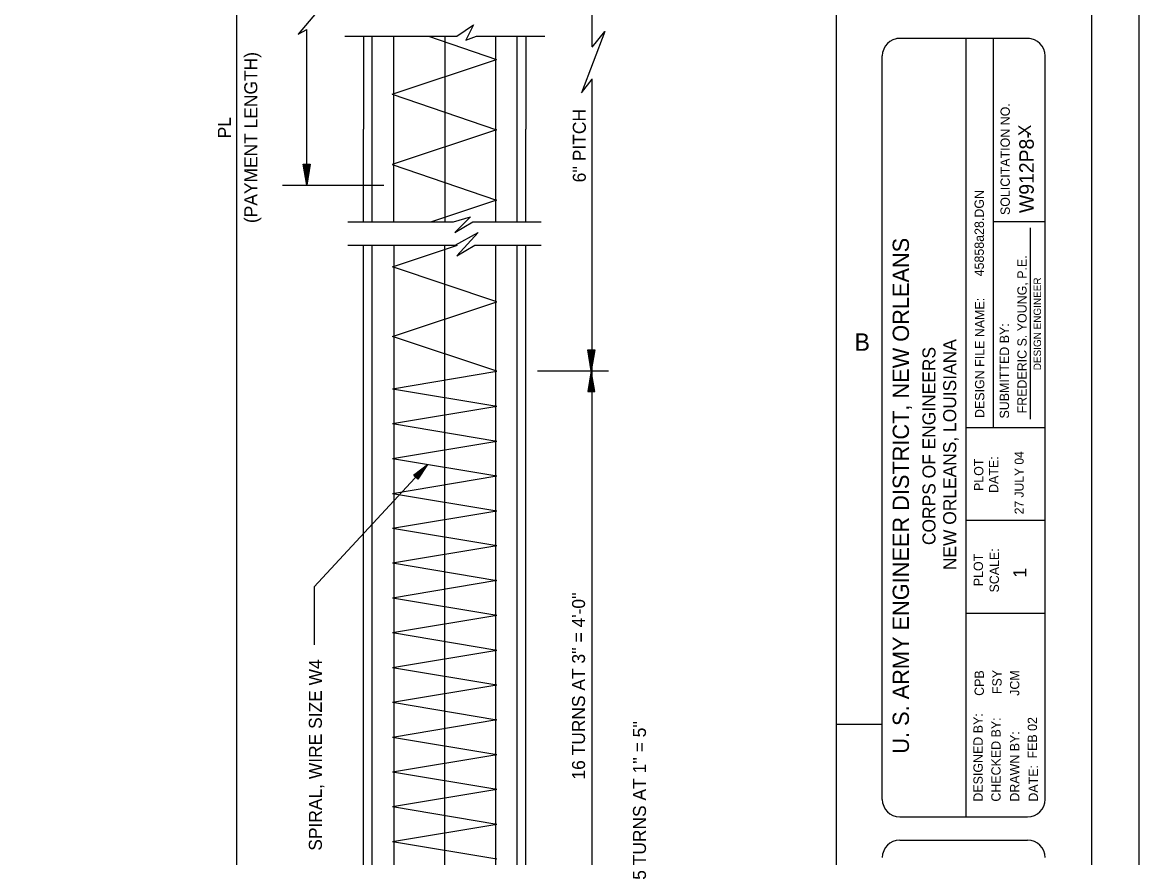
# Model space of a CAD drawing. Extents: x 22369.62 to 22373.29, y 22366.31 to 22369.14.
# Drawn here: x 22372.285 to 22373.287, y 22366.918 to 22367.667 of the extents above; entities that cross this region are included whole.
import ezdxf

# ---------------------------------------------------------------- set-up
doc = ezdxf.new("R2010")
doc.units = 0
for name, color, linetype in [('Level 1', 7, 'Continuous'), ('Level 10', 7, 'Continuous'), ('Level 2', 7, 'Continuous'), ('Level 3', 7, 'Continuous'), ('Level 4', 7, 'Continuous'), ('Level 7', 7, 'Continuous'), ('Level 9', 7, 'Continuous')]:
    doc.layers.add(name, color=color, linetype=linetype)

msp = doc.modelspace()

# ---------------------------------------------------------------- linework, layer by layer
at = {"layer": 'Level 1'}
for p, q in [((22373.1887, 22367.6522), (22373.0697, 22367.6522)), ((22373.1317, 22367.6522), (22373.1317, 22366.9542))]:
    msp.add_line(p, q, dxfattribs=at)
msp.add_lwpolyline([(22369.6213, 22369.1422), (22373.2867, 22369.1422), (22373.2867, 22366.3082), (22369.6213, 22366.3082)], close=True, dxfattribs=at)
for points in [[(22373.1871, 22367.6522), (22373.0723, 22367.6522)], [(22373.0567, 22366.9698), (22373.0567, 22367.6366)], [(22373.2027, 22366.9698), (22373.2027, 22367.6366)], [(22373.0723, 22366.9542), (22373.1871, 22366.9542)], [(22373.0723, 22366.9332), (22373.1871, 22366.9332)]]:
    msp.add_lwpolyline(points, dxfattribs=at)
for centre, start, end in [((22373.0723, 22367.6366), 90, 180), ((22373.1871, 22367.6366), 0, 90), ((22373.0723, 22366.9698), 180, 270), ((22373.1871, 22366.9698), 270, 0), ((22373.0723, 22366.9176), 90, 180), ((22373.1871, 22366.9176), 0, 90)]:
    msp.add_arc(centre, 0.0156, start, end, dxfattribs=at)
at = {"layer": 'Level 10'}
for p, q in [((22372.6186, 22367.4877), (22372.6186, 22367.6543)), ((22372.6496, 22367.6543), (22372.7107, 22367.6335)), ((22372.6641, 22367.6543), (22372.6641, 22367.4877)), ((22372.7097, 22367.6543), (22372.7097, 22367.4877)), ((22372.617, 22367.6022), (22372.7107, 22367.6335)), ((22372.617, 22367.6022), (22372.7107, 22367.5703)), ((22372.7107, 22367.5703), (22372.617, 22367.5391)), ((22372.617, 22367.5391), (22372.7107, 22367.5071)), ((22372.7107, 22367.5071), (22372.6524, 22367.4877)), ((22372.6172, 22367.4475), (22372.6756, 22367.4669)), ((22372.6186, 22367.4669), (22372.6186, 22366.7915)), ((22372.6641, 22366.7915), (22372.6641, 22367.4669)), ((22372.7097, 22367.4669), (22372.7097, 22366.7915)), ((22372.711, 22367.4162), (22372.6172, 22367.4475)), ((22372.6172, 22367.385), (22372.711, 22367.4162)), ((22372.711, 22367.3538), (22372.6172, 22367.385)), ((22372.6172, 22367.338), (22372.711, 22367.3538)), ((22372.6172, 22367.338), (22372.711, 22367.3224)), ((22372.6172, 22367.3068), (22372.711, 22367.3224)), ((22372.6172, 22367.3068), (22372.711, 22367.2912)), ((22372.6172, 22367.2756), (22372.711, 22367.2912)), ((22372.6172, 22367.2756), (22372.711, 22367.2599)), ((22372.6172, 22367.2443), (22372.711, 22367.26)), ((22372.6172, 22367.2443), (22372.711, 22367.2287)), ((22372.6172, 22367.2131), (22372.711, 22367.2287)), ((22372.6172, 22367.2131), (22372.711, 22367.1975)), ((22372.6172, 22367.1819), (22372.711, 22367.1975)), ((22372.6172, 22367.1819), (22372.711, 22367.1662)), ((22372.6172, 22367.1507), (22372.711, 22367.1663)), ((22372.6172, 22367.1507), (22372.711, 22367.135)), ((22372.6172, 22367.1194), (22372.711, 22367.135)), ((22372.6172, 22367.1194), (22372.711, 22367.1038)), ((22372.6172, 22367.0882), (22372.711, 22367.1038)), ((22372.6172, 22367.0882), (22372.711, 22367.0726)), ((22372.6172, 22367.057), (22372.711, 22367.0726)), ((22372.6172, 22367.057), (22372.711, 22367.0413)), ((22372.6172, 22367.0257), (22372.711, 22367.0414)), ((22373.0157, 22367.0372), (22373.0567, 22367.0372)), ((22372.6172, 22367.0257), (22372.711, 22367.0101)), ((22372.6172, 22366.9945), (22372.711, 22367.0101)), ((22372.6172, 22366.9945), (22372.711, 22366.9789)), ((22372.6172, 22366.9633), (22372.711, 22366.9789)), ((22372.6172, 22366.9633), (22372.711, 22366.9476)), ((22372.6172, 22366.932), (22372.711, 22366.9477)), ((22372.6172, 22366.932), (22372.711, 22366.9164))]:
    msp.add_line(p, q, dxfattribs=at)
at = {"layer": 'Level 2'}
for p, q in [((22372.6751, 22367.6543), (22372.6898, 22367.6645)), ((22372.6898, 22367.6645), (22372.6831, 22367.6506)), ((22372.5746, 22367.6543), (22372.6751, 22367.6543)), ((22372.5912, 22367.6543), (22372.5912, 22367.571)), ((22372.599, 22367.4877), (22372.599, 22367.6543)), ((22372.6831, 22367.6506), (22372.6927, 22367.6543)), ((22372.6927, 22367.6543), (22372.7539, 22367.6543)), ((22372.7292, 22367.4877), (22372.7292, 22367.6543)), ((22372.737, 22367.6543), (22372.737, 22367.571)), ((22373.1563, 22367.6522), (22373.1563, 22367.3032)), ((22372.5912, 22367.4877), (22372.5912, 22367.571)), ((22372.737, 22367.4877), (22372.737, 22367.571)), ((22373.1901, 22367.5098), (22373.1901, 22367.5098)), ((22372.5772, 22367.4877), (22372.6721, 22367.4877)), ((22372.6721, 22367.4877), (22372.6872, 22367.4924)), ((22372.6872, 22367.4924), (22372.6731, 22367.4781)), ((22372.6731, 22367.4781), (22372.6892, 22367.4877)), ((22372.6892, 22367.4877), (22372.7505, 22367.4877)), ((22373.2027, 22367.4879), (22373.1563, 22367.4879)), ((22372.6734, 22367.4669), (22372.6942, 22367.4782)), ((22372.6942, 22367.4782), (22372.6751, 22367.4572)), ((22373.1897, 22367.3107), (22373.1897, 22367.4825)), ((22372.5772, 22367.4669), (22372.6734, 22367.4669)), ((22372.5912, 22366.7993), (22372.5912, 22367.4669)), ((22372.599, 22366.7915), (22372.599, 22367.4669)), ((22372.6751, 22367.4572), (22372.6911, 22367.4669)), ((22372.6911, 22367.4669), (22372.7505, 22367.4669)), ((22372.7292, 22366.7915), (22372.7292, 22367.4669)), ((22372.737, 22366.7993), (22372.737, 22367.4669)), ((22373.2027, 22367.3032), (22373.1317, 22367.3032)), ((22373.2027, 22367.2198), (22373.1317, 22367.2198)), ((22373.2027, 22367.1365), (22373.1317, 22367.1365))]:
    msp.add_line(p, q, dxfattribs=at)
at = {"layer": 'Level 3'}
for p, q in [((22372.4777, 22366.79), (22372.4777, 22368.3502)), ((22372.7964, 22367.6448), (22372.7964, 22368.288)), ((22372.5492, 22367.6755), (22372.5327, 22367.656)), ((22372.5327, 22367.656), (22372.5405, 22367.6602)), ((22372.5405, 22367.52), (22372.5405, 22367.6602)), ((22372.8077, 22367.6585), (22372.7869, 22367.6034)), ((22372.7964, 22367.6446), (22372.8077, 22367.6585)), ((22372.7869, 22367.6034), (22372.7964, 22367.6158)), ((22372.7964, 22366.7497), (22372.7964, 22367.616)), ((22372.5372, 22367.5394), (22372.5434, 22367.5394)), ((22372.5403, 22367.5207), (22372.5372, 22367.5394)), ((22372.54, 22367.5391), (22372.5376, 22367.5391)), ((22372.5376, 22367.5391), (22372.54, 22367.5245)), ((22372.54, 22367.5387), (22372.5381, 22367.5388)), ((22372.5381, 22367.5388), (22372.5397, 22367.5281)), ((22372.5396, 22367.5383), (22372.5385, 22367.5383)), ((22372.5385, 22367.5383), (22372.5393, 22367.533)), ((22372.5393, 22367.533), (22372.5392, 22367.538)), ((22372.5397, 22367.5281), (22372.5396, 22367.5383)), ((22372.54, 22367.5245), (22372.54, 22367.5387)), ((22372.5403, 22367.5207), (22372.5403, 22367.5394)), ((22372.5434, 22367.5394), (22372.5403, 22367.5207)), ((22372.543, 22367.5391), (22372.5406, 22367.5245)), ((22372.5406, 22367.5245), (22372.5407, 22367.5387)), ((22372.5407, 22367.5391), (22372.543, 22367.5391)), ((22372.5407, 22367.5387), (22372.5426, 22367.5386)), ((22372.5426, 22367.5386), (22372.5409, 22367.5281)), ((22372.5409, 22367.5281), (22372.541, 22367.5383)), ((22372.541, 22367.5383), (22372.5421, 22367.5383)), ((22372.5421, 22367.5383), (22372.5413, 22367.533)), ((22372.5413, 22367.533), (22372.5414, 22367.538)), ((22372.6094, 22367.5205), (22372.5185, 22367.5205)), ((22372.7925, 22367.373), (22372.7987, 22367.373)), ((22372.7956, 22367.3543), (22372.7925, 22367.373)), ((22372.7953, 22367.3727), (22372.7929, 22367.3727)), ((22372.7929, 22367.3727), (22372.7953, 22367.3582)), ((22372.7953, 22367.3724), (22372.7934, 22367.3724)), ((22372.7934, 22367.3724), (22372.795, 22367.3618)), ((22372.795, 22367.3719), (22372.7938, 22367.372)), ((22372.7938, 22367.372), (22372.7946, 22367.3666)), ((22372.7946, 22367.3666), (22372.7945, 22367.3716)), ((22372.795, 22367.3618), (22372.795, 22367.3719)), ((22372.7953, 22367.3582), (22372.7953, 22367.3724)), ((22372.7956, 22367.3543), (22372.7956, 22367.373)), ((22372.7987, 22367.373), (22372.7956, 22367.3543)), ((22372.7983, 22367.3727), (22372.7959, 22367.3581)), ((22372.7959, 22367.3581), (22372.796, 22367.3723)), ((22372.796, 22367.3727), (22372.7983, 22367.3727)), ((22372.796, 22367.3723), (22372.7979, 22367.3723)), ((22372.7979, 22367.3723), (22372.7962, 22367.3617)), ((22372.7962, 22367.3617), (22372.7964, 22367.3719)), ((22372.7964, 22367.3719), (22372.7974, 22367.3719)), ((22372.7974, 22367.3719), (22372.7966, 22367.3666)), ((22372.7966, 22367.3666), (22372.7967, 22367.3716)), ((22372.7474, 22367.3543), (22372.8112, 22367.3543)), ((22372.7956, 22367.3543), (22372.7925, 22367.3356)), ((22372.7929, 22367.3358), (22372.7953, 22367.3504)), ((22372.7934, 22367.3362), (22372.795, 22367.3468)), ((22372.795, 22367.3468), (22372.795, 22367.3367)), ((22372.7953, 22367.3504), (22372.7953, 22367.3362)), ((22372.7956, 22367.3543), (22372.7956, 22367.3356)), ((22372.7987, 22367.3356), (22372.7956, 22367.3543)), ((22372.7983, 22367.3359), (22372.7959, 22367.3505)), ((22372.7959, 22367.3505), (22372.796, 22367.3362)), ((22372.7979, 22367.3363), (22372.7962, 22367.3469)), ((22372.7962, 22367.3469), (22372.7964, 22367.3366)), ((22372.7953, 22367.3359), (22372.7929, 22367.3358)), ((22372.7953, 22367.3362), (22372.7934, 22367.3362)), ((22372.7938, 22367.3366), (22372.7946, 22367.342)), ((22372.795, 22367.3367), (22372.7938, 22367.3366)), ((22372.7946, 22367.342), (22372.7945, 22367.337)), ((22372.796, 22367.3362), (22372.7979, 22367.3363)), ((22372.796, 22367.3359), (22372.7983, 22367.3359)), ((22372.7964, 22367.3366), (22372.7974, 22367.3366)), ((22372.7974, 22367.3366), (22372.7966, 22367.342)), ((22372.7966, 22367.342), (22372.7967, 22367.337)), ((22372.7925, 22367.3356), (22372.7987, 22367.3356)), ((22372.547, 22367.1606), (22372.6487, 22367.2702)), ((22372.6458, 22367.267), (22372.6458, 22367.267)), ((22372.6487, 22367.2702), (22372.6487, 22367.2702)), ((22372.547, 22367.1606), (22372.547, 22367.1083))]:
    msp.add_line(p, q, dxfattribs=at)
msp.add_lwpolyline([(22372.6362, 22367.2605), (22372.6487, 22367.2702), (22372.64, 22367.257), (22372.6368, 22367.26), (22372.6458, 22367.267), (22372.6399, 22367.258), (22372.6378, 22367.26), (22372.6429, 22367.2639), (22372.6397, 22367.2591), (22372.6389, 22367.2599), (22372.64, 22367.2607)], dxfattribs=at)
at = {"layer": 'Level 9'}
msp.add_line((22373.2447, 22366.3502), (22373.2447, 22369.1002), dxfattribs=at)
msp.add_lwpolyline([(22373.0157, 22366.3502), (22373.0157, 22369.1002)], dxfattribs=at)

# ---------------------------------------------------------------- texts
at = {"layer": 'Level 1'}
for s, height, p in [('SOLICITATION NO.', 0.008334, (22373.1711, 22367.4939)), ('U. S. ARMY ENGINEER DISTRICT, NEW ORLEANS', 0.014583, (22373.0806, 22367.0108)), ('DESIGN ENGINEER', 0.006666, (22373.1991, 22367.3547)), ('DESIGN FILE NAME:', 0.008334, (22373.1482, 22367.3119)), ('SUBMITTED BY:', 0.008334, (22373.1704, 22367.3114)), ('DATE:', 0.00833, (22373.1607, 22367.2447)), ('PLOT', 0.00833, (22373.1474, 22367.2464)), ('PLOT', 0.00833, (22373.147, 22367.161)), ('SCALE:', 0.00833, (22373.1613, 22367.1554)), ('DESIGNED BY:', 0.008334, (22373.1468, 22366.9678)), ('CHECKED BY:', 0.008334, (22373.1628, 22366.9678)), ('DRAWN BY:', 0.00833, (22373.1796, 22366.9678)), ('DATE:', 0.00833, (22373.1963, 22366.9678))]:
    msp.add_text(s, height=height, rotation=90, dxfattribs=at).set_placement(p)
msp.add_text('B', height=0.0156, dxfattribs=at).set_placement((22373.0317, 22367.3722))
at = {"layer": 'Level 2'}
for s, height, p in [('45858a28.DGN', 0.008333, (22373.1478, 22367.4389)), ('FREDERIC S. YOUNG, P.E.', 0.008333, (22373.1862, 22367.316)), ('FSY', 0.00833, (22373.1637, 22367.0643)), ('CPB', 0.00833, (22373.1478, 22367.0627)), ('JCM', 0.00833, (22373.1796, 22367.0627)), ('FEB 02', 0.00833, (22373.1955, 22367.0065))]:
    msp.add_text(s, height=height, rotation=90, dxfattribs=at).set_placement(p)
at = {"layer": 'Level 4'}
for s, height, p in [('(PAYMENT LENGTH)', 0.011667, (22372.496, 22367.4867)), ("6'' PITCH", 0.01167, (22372.7907, 22367.5232)), ('PL', 0.01167, (22372.4723, 22367.5627)), ("16 TURNS AT 3'' = 4'-0''", 0.011667, (22372.79, 22366.9876)), ('SPIRAL, WIRE SIZE W4', 0.011667, (22372.5539, 22366.9238)), ("5 TURNS AT 1'' = 5''", 0.011667, (22372.8447, 22366.8977))]:
    msp.add_text(s, height=height, rotation=90, dxfattribs=at).set_placement(p)
at = {"layer": 'Level 7'}
for s, height, p in [('X', 0.0114, (22373.1902, 22367.5648)), ('W912P8-', 0.013, (22373.1926, 22367.4957)), ('NEW ORLEANS, LOUISIANA', 0.011666, (22373.123, 22367.1754)), ('CORPS OF ENGINEERS', 0.011666, (22373.1044, 22367.1979)), ('27 JULY 04', 0.0081, (22373.1835, 22367.2255)), ('1', 0.0117, (22373.1859, 22367.1687))]:
    msp.add_text(s, height=height, rotation=90, dxfattribs=at).set_placement(p)

doc.saveas('drawing.dxf')
